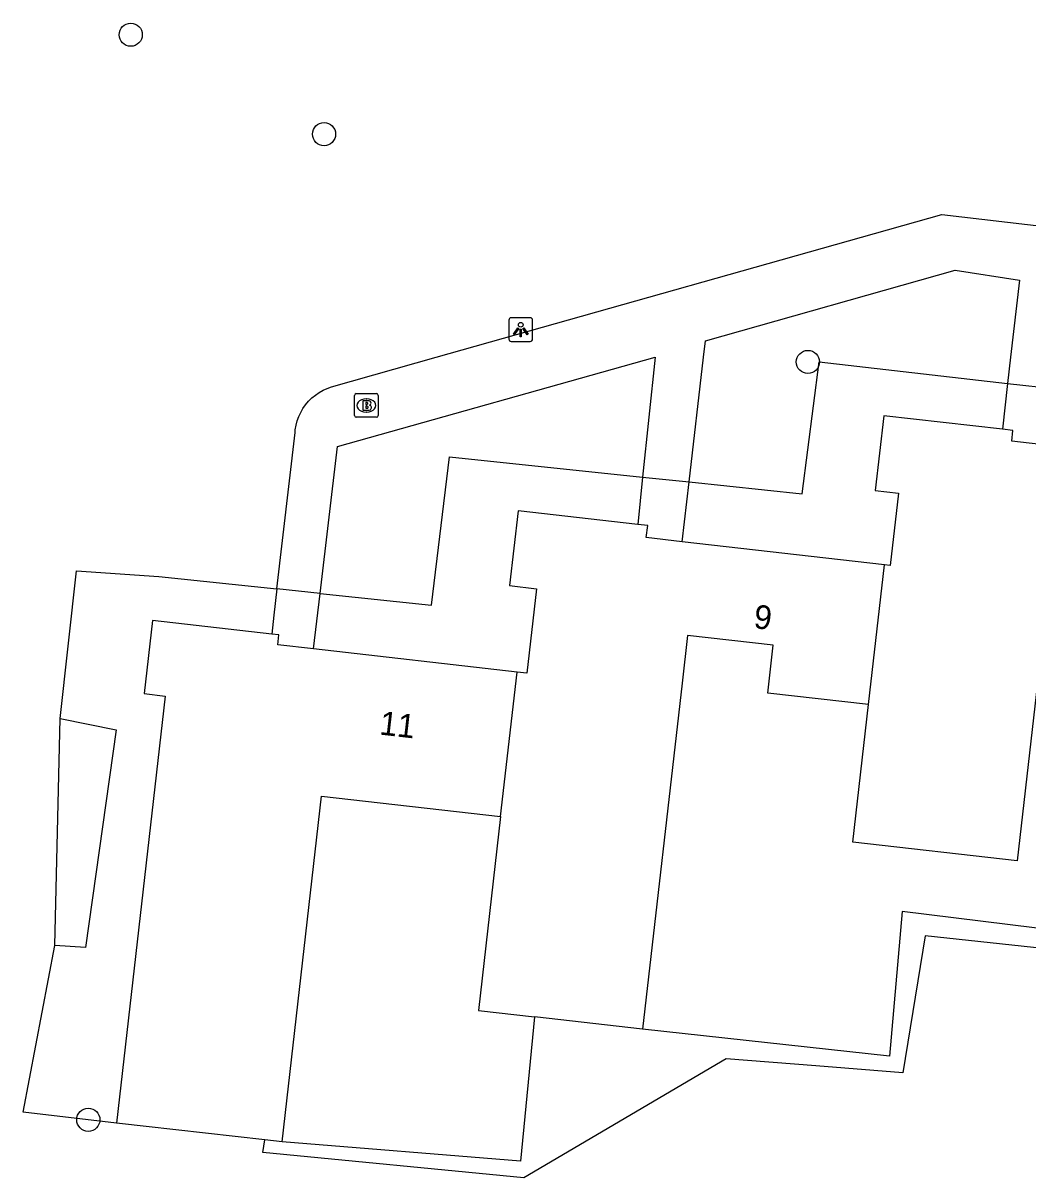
# Model space of a CAD drawing. Extents: x 162186 to 163152, y 385513 to 386513.
# Drawn here: x 162250.32 to 162292.76, y 385965.35 to 386014.11 of the extents above; entities that cross this region are included whole.
import ezdxf

# ---------------------------------------------------------------- set-up
doc = ezdxf.new("R2010")
doc.units = 0
for name, color, linetype in [('IMGEO_Boom', 7, 'Continuous'), ('IMGEO_Brandkraan', 7, 'Continuous'), ('IMGEO_Groenvoorziening', 7, 'Continuous'), ('IMGEO_Lichtpunt', 7, 'Continuous'), ('IMGEO_Pand', 7, 'Continuous'), ('IMGEO_Pand_nummerreeks', 7, 'Continuous'), ('IMGEO_Voetpad_open', 7, 'Continuous')]:
    doc.layers.add(name, color=color, linetype=linetype)

msp = doc.modelspace()

# ---------------------------------------------------------------- linework, layer by layer
at = {"layer": 'IMGEO_Boom'}
for centre in [(162254.865, 386013.624), (162263.03, 386009.424), (162283.468, 385999.804), (162253.073, 385967.805)]:
    msp.add_circle(centre, 0.489, dxfattribs=at)
at = {"layer": 'IMGEO_Brandkraan'}
for p, q in [((162264.393, 385998.469), (162265.245, 385998.469)), ((162264.318, 385997.543), (162264.318, 385998.395)), ((162264.806, 385998.249), (162264.831, 385998.249)), ((162265.319, 385998.395), (162265.319, 385997.543)), ((162265.245, 385997.469), (162264.393, 385997.469)), ((162264.829, 385997.689), (162264.804, 385997.689))]:
    msp.add_line(p, q, dxfattribs=at)
for points in [[(162264.393, 385998.469), (162265.245, 385998.469)], [(162264.318, 385997.543), (162264.318, 385998.395)], [(162264.666, 385998.169), (162264.666, 385997.769), (162264.879, 385997.769)], [(162264.897, 385998.169), (162264.666, 385998.169)], [(162264.845, 385998.088), (162264.791, 385998.088), (162264.791, 385998.012)], [(162264.791, 385998.012), (162264.844, 385998.012)], [(162264.853, 385997.936), (162264.791, 385997.936), (162264.791, 385997.855)], [(162265.319, 385998.395), (162265.319, 385997.543)], [(162265.245, 385997.469), (162264.393, 385997.469)], [(162264.791, 385997.855), (162264.853, 385997.855)]]:
    msp.add_lwpolyline(points, dxfattribs=at)
for centre, radius, start, end in [((162264.395, 385998.393), 0.0765, 91.552, 178.448), ((162264.395, 385998.393), 0.0765, 91.552, 178.448), ((162265.243, 385998.393), 0.0765, 1.552, 88.448), ((162265.243, 385998.393), 0.0765, 1.552, 88.448), ((162264.846, 385998.05), 0.0379, 267.8285, 90.9355), ((162264.854, 385997.895), 0.0404, 269.8759, 90.5077), ((162264.901, 385998.024), 0.145, 59.4692, 91.5367), ((162264.926, 385998.071), 0.0922, 285.5137, 58.1501), ((162264.931, 385997.879), 0.105, 301.3115, 78.989), ((162264.395, 385997.545), 0.0765, 181.552, 268.448), ((162264.395, 385997.545), 0.0765, 181.552, 268.448), ((162264.885, 385998.02), 0.251, 268.6676, 293.5347), ((162265.243, 385997.545), 0.0765, 271.552, 358.448), ((162265.243, 385997.545), 0.0765, 271.552, 358.448)]:
    msp.add_arc(centre, radius, start, end, dxfattribs=at)
for centre, major_axis, ratio, start_param, end_param in [((162264.805, 385997.969), (-0.387, 0.002), 0.722429, 4.712389, 7.853982), ((162264.83, 385997.969), (-0.39, 0.002), 0.717154, 1.570796, 4.712389)]:
    msp.add_ellipse(centre, major_axis=major_axis, ratio=ratio, start_param=start_param, end_param=end_param, dxfattribs=at)
at = {"layer": 'IMGEO_Groenvoorziening'}
for points in [[(162278.451, 385994.737), (162283.222, 385994.239), (162283.948, 385999.809), (162291.903, 385998.9)], [(162262.867, 385990.032), (162267.574, 385989.537), (162268.333, 385995.794), (162276.488, 385994.942)], [(162251.883, 385984.747), (162252.58, 385990.983), (162256.046, 385990.75), (162261.039, 385990.225)], [(162251.663, 385975.16), (162251.883, 385984.747)], [(162251.883, 385984.747), (162254.245, 385984.27), (162252.958, 385975.074), (162251.663, 385975.16)], [(162299.886, 385975.071), (162287.447, 385976.602), (162286.919, 385970.497), (162276.485, 385971.632)], [(162299.803, 385974.348), (162288.426, 385975.573), (162287.474, 385969.793), (162283.808, 385970.078), (162280.02, 385970.373), (162271.463, 385965.351), (162260.441, 385966.418), (162260.526, 385966.955)], [(162254.265, 385967.669), (162250.317, 385968.131), (162251.663, 385975.16)], [(162271.926, 385972.152), (162271.323, 385966.057), (162261.262, 385966.871)]]:
    msp.add_lwpolyline(points, dxfattribs=at)
at = {"layer": 'IMGEO_Lichtpunt'}
for p, q in [((162270.84, 386001.576), (162270.84, 386000.769)), ((162270.84, 386001.576), (162270.84, 386000.769)), ((162271.742, 386001.671), (162270.934, 386001.671)), ((162271.742, 386001.671), (162270.934, 386001.671)), ((162271.836, 386000.769), (162271.836, 386001.576)), ((162271.836, 386000.769), (162271.836, 386001.576)), ((162270.934, 386000.675), (162271.742, 386000.675)), ((162270.934, 386000.675), (162271.742, 386000.675))]:
    msp.add_line(p, q, dxfattribs=at)
for points in [[(162271.214, 386001.24), (162271.253, 386001.212), (162271.065, 386000.95), (162271.027, 386000.977), (162271.214, 386001.24)], [(162271.316, 386001.192), (162271.363, 386001.192), (162271.363, 386000.87), (162271.316, 386000.87), (162271.316, 386001.192)], [(162271.426, 386001.212), (162271.464, 386001.239), (162271.651, 386000.977), (162271.612, 386000.949), (162271.426, 386001.212)]]:
    msp.add_lwpolyline(points, dxfattribs=at)
msp.add_circle((162271.339, 386001.374), 0.0994, dxfattribs=at)
for centre, start, end in [((162270.934, 386001.576), 90, 180), ((162270.934, 386001.576), 90, 180), ((162271.742, 386001.576), 0, 90), ((162271.742, 386001.576), 0, 90), ((162270.934, 386000.769), 180, 270), ((162270.934, 386000.769), 180, 270), ((162271.742, 386000.769), 270, 0), ((162271.742, 386000.769), 270, 360)]:
    msp.add_arc(centre, 0.0946, start, end, dxfattribs=at)
at = {"layer": 'IMGEO_Pand'}
for points in [[(162291.682, 385996.964), (162286.674, 385997.536), (162286.314, 385994.382), (162287.294, 385994.27), (162286.945, 385991.211), (162286.705, 385991.238)], [(162293.676, 385996.279), (162292.077, 385996.461), (162292.129, 385996.913), (162291.682, 385996.964)], [(162276.279, 385992.947), (162271.228, 385993.524), (162270.867, 385990.36), (162271.998, 385990.231), (162271.592, 385986.664), (162271.186, 385986.71)], [(162278.159, 385992.214), (162276.642, 385992.387), (162276.701, 385992.899), (162276.279, 385992.947)], [(162286.705, 385991.238), (162278.159, 385992.214)], [(162301.528, 385989.428), (162297.183, 385989.924), (162297.406, 385991.882), (162293.879, 385992.284), (162293.63, 385990.329), (162292.306, 385978.734), (162285.367, 385979.526), (162286.03, 385985.339)], [(162286.03, 385985.339), (162286.705, 385991.238)], [(162260.818, 385988.316), (162255.78, 385988.891), (162255.427, 385985.8), (162256.322, 385985.698), (162254.265, 385967.669)], [(162262.59, 385987.691), (162261.071, 385987.865), (162261.114, 385988.276), (162260.818, 385988.316)], [(162286.03, 385985.339), (162281.773, 385985.825), (162282.003, 385987.842), (162278.382, 385988.255), (162278.152, 385986.238), (162276.485, 385971.632)], [(162271.186, 385986.71), (162262.59, 385987.691)], [(162270.485, 385980.615), (162271.186, 385986.71)], [(162261.262, 385966.871), (162262.929, 385981.477), (162270.485, 385980.615)], [(162270.485, 385980.615), (162269.551, 385972.423), (162271.926, 385972.152)], [(162276.485, 385971.632), (162271.926, 385972.152)], [(162260.526, 385966.955), (162254.265, 385967.669)], [(162261.262, 385966.871), (162260.526, 385966.955)]]:
    msp.add_lwpolyline(points, dxfattribs=at)
at = {"layer": 'IMGEO_Voetpad_open'}
for points in [[(162261.039, 385990.225), (162261.804, 385996.819), (162261.816, 385996.943), (162261.848, 385997.133), (162261.897, 385997.32), (162261.962, 385997.501), (162262.044, 385997.676), (162262.14, 385997.843), (162262.252, 385998.001), (162262.377, 385998.148), (162262.514, 385998.283), (162262.663, 385998.406), (162262.823, 385998.515), (162262.991, 385998.609), (162263.167, 385998.687), (162263.35, 385998.75), (162267.773, 386000), (162289.13, 386006.035), (162311.682, 386003.405)], [(162278.451, 385994.737), (162279.061, 386000), (162279.141, 386000.694), (162289.684, 386003.676), (162292.401, 386003.263), (162292.029, 386000), (162291.903, 385998.9)], [(162262.867, 385990.032), (162263.6, 385996.24), (162277.018, 386000), (162276.488, 385994.942)], [(162291.903, 385998.9), (162291.682, 385996.964)], [(162291.903, 385998.9), (162293.965, 385998.665)], [(162276.488, 385994.942), (162276.279, 385992.947)], [(162276.488, 385994.942), (162278.451, 385994.737)], [(162278.159, 385992.214), (162278.451, 385994.737)], [(162261.039, 385990.225), (162260.91, 385989.111), (162260.818, 385988.316)], [(162262.867, 385990.032), (162261.039, 385990.225)], [(162262.59, 385987.691), (162262.867, 385990.032)]]:
    msp.add_lwpolyline(points, dxfattribs=at)

# ---------------------------------------------------------------- texts
at = {"layer": 'IMGEO_Pand_nummerreeks'}
for s, p in [('9', (162281.148, 385988.571)), ('11', (162265.341, 385984.076))]:
    msp.add_text(s, height=1, rotation=353.4912, dxfattribs=at).set_placement(p)

doc.saveas('drawing.dxf')
